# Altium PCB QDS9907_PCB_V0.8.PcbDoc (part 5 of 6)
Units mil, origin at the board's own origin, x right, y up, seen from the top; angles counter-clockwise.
Board outline 3410.03 x 4010.03 mil, 8 copper layers (Top Layer, GND1, INT1, INT2, PWR1, GND2, GND3, Bottom Layer), stack 81.668 mil thick; 250 components, 129 nets, 7010 pads, 701 vias.
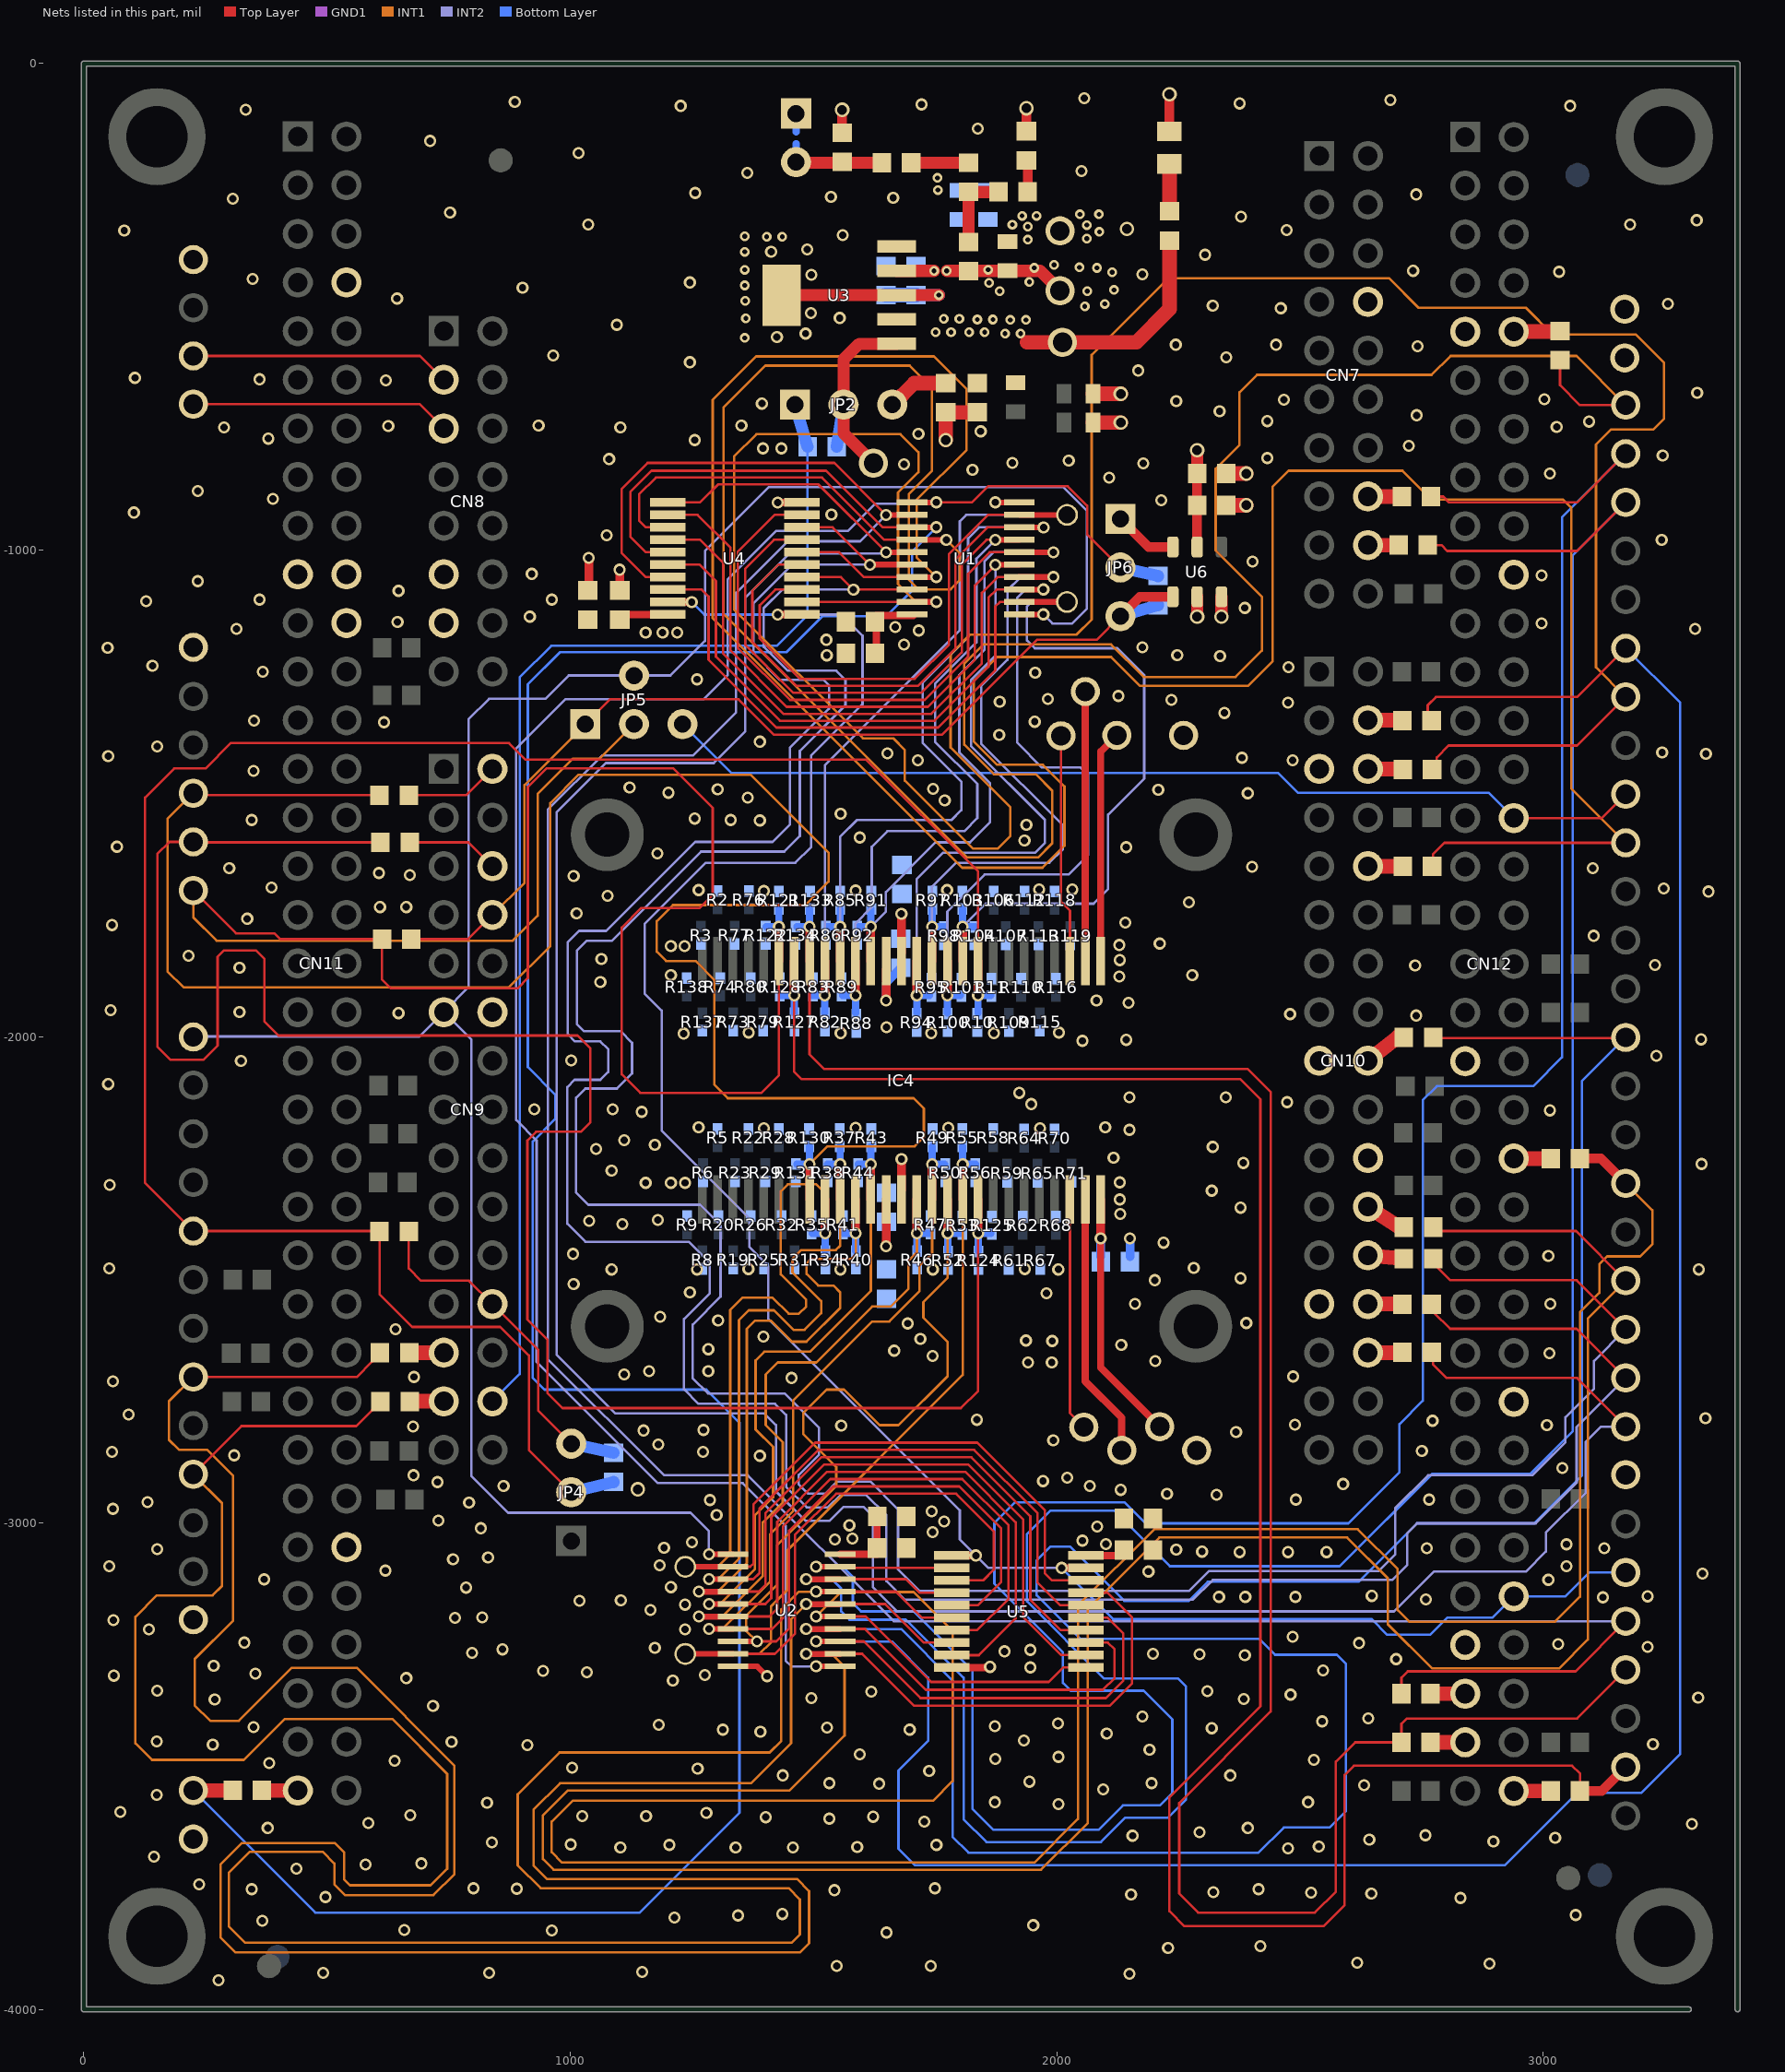
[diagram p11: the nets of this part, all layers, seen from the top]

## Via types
v1: diameter 25, hole 15, Top Layer to Bottom Layer, tented both sides, 623 vias
v2: diameter 20, hole 10, Top Layer to Bottom Layer, tented both sides, 59 vias
v3: diameter 30, hole 20, Top Layer to Bottom Layer, tented both sides, 19 vias

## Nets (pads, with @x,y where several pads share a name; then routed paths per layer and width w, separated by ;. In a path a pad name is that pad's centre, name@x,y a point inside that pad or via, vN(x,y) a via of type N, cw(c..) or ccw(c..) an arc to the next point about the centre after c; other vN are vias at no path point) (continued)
D0: IC4.9 pad.@1236.55,-3090.09 R34.2 R35.2 U2.2 U5.18 | length 2561.7
  Top Layer w5: U2.2@1334.53,-3090.09 1369.91,-3090.09 1377,-3083 1377,-2961.51 1503.51,-2835 1837,-2835 1976,-2974 1976,-3104 1990.18,-3118.18 U5.18@2060,-3118.18
  Top Layer w11.8: pad.@1236.55,-3090.09 U2.2@1334.08,-3090.09
  Top Layer w18: v1@1523.52,-2404.54 IC4.9@1523.52,-2335
  INT1 w5: pad.@1236.55,-3090.09 1302.91,-3090.09 1329,-3064 1329,-2562 1354,-2537 1416,-2537 1449,-2570 1470,-2570 1485,-2555 1485,-2541 1433,-2489 1433,-2318 1447,-2304 1506,-2304 1523.97,-2321.97 v1(1523.97,-2404.54)
  Bottom Layer w15: R35.2@1497.89,-2404.54 v1(1523.97,-2404.54) R34.2@1523.97,-2440.54
D0_1: D0.1 R33.1 U2.19 U5.2 | length 6029.7
  Top Layer w5: U2.19@1555,-3090.09 1555,-3092.59 U5.2@1784.41,-3092.59 ; R33.1@2763,-890 2795,-890 2807,-902 3070,-902 D0.1@3170,-802
  Top Layer w11.8: v1@1505.33,-3090.09 U2.19@1554.55,-3090.09
  Bottom Layer w5: v1(1505.63,-3090.24) 1560.24,-3090.24 1581,-3111 1581,-3165.05 1597.95,-3182 1706,-3182 1827,-3303 1827,-3588 1870,-3631 2086,-3631 2136.5,-3580.5 2212.5,-3580.5 2238,-3555 2238,-3404 2179,-3345 2029,-3345 2013,-3329 2013,-3266 1872,-3125 1872,-3000 1914,-2958 2140,-2958 2183,-3001 2600,-3001 2705,-2896 2705,-2797 2753,-2749 2753,-2131 2782,-2102 2980,-2102 3039,-2043 3039,-933 D0.1@3170,-802
D0_2: CN7.16 R33.2 | length 63
  Top Layer w30: CN7.16@2640,-890 R33.2@2703,-890
D1: IC4.10 R37.2 R38.2 U2.3 U5.16 | length 2503.8
  Top Layer w5: U2.3@1334.53,-3115.68 1376.32,-3115.68 1389.14,-3102.86 1389.14,-2970.58 1509.72,-2850 1830.79,-2850 1961,-2980.21 1961,-3123 2007.36,-3169.36 U5.16@2060,-3169.36
  Top Layer w11.8: v1@1284.86,-3115.68 U2.3@1334.08,-3115.68
  Top Layer w18: IC4.10@1555.02,-2335 v1(1555.02,-2262.46)
  INT1 w5: v1(1285.15,-3115.83) 1304.71,-3115.83 1347,-3073.54 1347,-2583 1367,-2563 1419,-2563 1459,-2603 1482,-2603 1516,-2569 1516,-2544 1457,-2485 1457,-2457 1475,-2439 1546,-2439 1555.02,-2429.98 v1(1555.02,-2262.46)
  Bottom Layer w15: R38.2@1528.94,-2262.46 v1(1555.02,-2262.46) R37.2@1555.02,-2226.46
D1_1: D1.1 R36.1 U2.18 U5.4 | length 6032.4
  Top Layer w5: U2.18@1555,-3115.68 1593.68,-3115.68 1690.05,-3115.68 1718.14,-3143.77 U5.4@1784.41,-3143.77 ; R36.1@2763,-990 2791,-990 2803,-1002 3070,-1002 D1.1@3170,-902
  Top Layer w11.8: v1(1485,-3115.84) U2.18@1554.7,-3115.84
  Bottom Layer w5: v1(1485,-3115.84) 1537.84,-3115.84 1557,-3135 1557,-3182 1574,-3199 1690,-3199 1809,-3318 1809,-3609 1856,-3656 2091,-3656 2141,-3606 2229,-3606 2266,-3569 2266,-3336 2250,-3320 2098,-3320 1939,-3161 1939,-3023 1987,-2975 2119,-2975 2233,-3089 2582,-3089 2772,-2899 2974,-2899 3061,-2812 3061,-1011 D1.1@3170,-902
D1_2: CN7.18 R36.2 | length 63
  Top Layer w30: CN7.18@2640,-990 R36.2@2703,-990
D2: IC4.11 R40.2 R41.2 U2.4 U5.14 | length 2516.7
  Top Layer w5: U2.4@1334.53,-3141.27 1387.73,-3141.27 1401.29,-3127.71 1401.29,-2979.65 1515.93,-2865 1824.58,-2865 1946,-2986.43 1946,-3158 2008.54,-3220.54 U5.14@2060,-3220.54
  Top Layer w11.8: v1@1264.08,-3141.43 v1(1264.53,-3141.43) U2.4@1334.23,-3141.43
  Top Layer w18: v1@1586.51,-2404.54 IC4.11@1586.51,-2335
  INT1 w5: v1(1264.53,-3141.43) 1303.58,-3141.43 1363,-3082 1363,-2601 1380,-2584 1412,-2584 1455.5,-2627.5 1485.5,-2627.5 1555,-2558 1555,-2526 1541,-2512 1510,-2512 1486,-2488 1486,-2466 1495,-2457 1577.96,-2457 1586.96,-2448 v1(1586.96,-2404.54)
  Bottom Layer w15: R41.2@1560.88,-2404.54 v1(1586.96,-2404.54) R40.2@1586.96,-2440.54
D2_1: D2.1 R39.1 U2.17 U5.6 | length 6065
  Top Layer w5: D2.1@225,-2700 561,-2700 592.5,-2668.5 592.5,-2667.5 605,-2655 R39.1@616,-2655 ; U2.17@1555,-3141.27 1669.27,-3141.27 1722.95,-3194.95 U5.6@1784.41,-3194.95
  Top Layer w11.8: v1@1505.33,-3141.27 U2.17@1554.55,-3141.27
  INT1 w5: D2.1@225,-2700 175,-2750 175,-2829 196,-2850 254,-2850 307,-2903 307,-3201 228,-3280 228,-3375 260,-3407 319,-3407 428,-3298 561,-3298 762,-3499 762,-3722 719,-3765 537,-3765 515,-3743 515,-3700 491,-3676 341,-3676 298,-3719 298,-3829 332,-3863 1455,-3863 1472,-3846 1472,-3774 1449,-3751 939,-3751 892,-3704 892,-3558 978,-3472 1410,-3472 1434,-3448 1434,-3178 1470.58,-3141.43 v1(1505.63,-3141.43)
D2_2: CN9.25 R39.2 | length 64
  Top Layer w30: R39.2@676,-2650 CN9.25@740,-2650
D3: IC4.12 R43.2 R44.2 U2.5 U5.12 | length 2545.8
  Top Layer w5: U2.5@1334.53,-3166.86 1401.14,-3166.86 1413.43,-3154.57 1413.43,-2988.72 1522.15,-2880 1818.36,-2880 1931,-2992.64 1931,-3193 2009.73,-3271.73 U5.12@2060,-3271.73
  Top Layer w11.8: v1@1285.15,-3166.86 U2.5@1334.53,-3166.86
  Top Layer w18: IC4.12@1618.01,-2335 v1(1618.01,-2262.46)
  INT1 w5: v1(1285.15,-3167.02) 1307.99,-3167.02 1380,-3095 1380,-2984 1417,-2947 1417,-2844 1381,-2808 1381,-2666 1399,-2648 1493,-2648 1618.01,-2522.99 v1(1618.01,-2262.46)
  Bottom Layer w15: R44.2@1591.93,-2262.46 v1(1618.01,-2262.46) R43.2@1618.01,-2226.46
D3_1: D3.1 R42.2 U2.16 U5.8 | length 6084.4
  Top Layer w5: D3.1@225,-2900 324,-2801 560,-2801 592.5,-2768.5 593.5,-2768.5 610,-2752 R42.2@610,-2751 ; U2.16@1555,-3166.86 1647.86,-3166.86 1727.13,-3246.13 U5.8@1784.41,-3246.13
  Top Layer w11.8: v1(1485,-3167.02) U2.16@1554.7,-3167.02
  INT1 w5: D3.1@237,-2900 D3.1@225,-2900 284,-2959 284,-3130 265,-3149 150,-3149 106,-3193 106,-3453 140,-3487 329,-3487 413,-3403 634,-3403 747,-3516 747,-3711 713,-3745 547,-3745 535,-3733 535,-3677 516,-3658 325,-3658 281,-3702 281,-3852 312,-3883 1472,-3883 1491,-3864 1491,-3757 1466,-3732 952,-3732 924.5,-3704.5 924.5,-3589.5 979,-3535 1372,-3535 1454,-3453 1454,-3198.02 v1(1485,-3167.02)
D3_2: CN9.27 R42.1 | length 63
  Top Layer w30: R42.1@677,-2750 CN9.27@740,-2750
D4: IC4.15 R46.2 R47.2 U2.6 U5.9 | length 2513.8
  Top Layer w5: U2.6@1334.53,-3192.45 1409.55,-3192.45 1425.57,-3176.43 1425.57,-2997.79 1528.36,-2895 1812.15,-2895 1916,-2998.85 1916,-3196 1840,-3272 1784.68,-3272 U5.9@1784.41,-3271.73
  Top Layer w11.8: v1@1264.08,-3192.61 v1(1264.53,-3192.61) U2.6@1334.23,-3192.61
  Top Layer w18: v1@1712.5,-2404.54 IC4.15@1712.5,-2335
  INT1 w5: v1(1264.53,-3192.61) 1312.39,-3192.61 1396,-3109 1396,-2999 1437,-2958 1437,-2834 1402,-2799 1402,-2695 1427,-2670 1506,-2670 1621,-2555 1659,-2555 1695,-2519 1695,-2462 1712.94,-2444.06 v1(1712.94,-2404.54)
  Bottom Layer w15: R46.2@1712.94,-2440.54 v1(1712.94,-2404.54) R47.2@1739.02,-2404.54
D4_1: D4.1 R45.1 U2.15 U5.11 | length 6088.9
  Top Layer w5: U2.15@1555,-3192.45 1607.45,-3192.45 1742,-3327 1984,-3327 2013.68,-3297.32 U5.11@2060,-3297.32
  Top Layer w11.8: v1@1505.33,-3192.45 U2.15@1554.55,-3192.45
  Top Layer w20: R45.1@3076,-2251 3119,-2251 D4.1@3170,-2302
  INT1 w5: v1(1505.63,-3192.61) 1556.23,-3142 1706,-3142 1786,-3222 1786,-3531 1746,-3571 1005,-3571 962,-3614 962,-3677 983,-3698 1954.47,-3698 2044,-3608.47 2044,-3170 2201,-3013 2619,-3013 2701,-3095 2701,-3179 2725,-3203 3025,-3203 3076,-3152 3076,-2567 3116,-2527 3116,-2468 3132,-2452 3200,-2452 3225,-2427 3225,-2357 D4.1@3170,-2302
D4_2: CN12.44 R45.2 | length 76
  Top Layer w30: CN12.44@2940,-2251 R45.2@3016,-2251
D5: IC4.16 R49.2 R50.2 U2.7 U5.7 | length 2504.4
  Top Layer w5: U2.7@1334.53,-3218.04 1414.96,-3218.04 1437.71,-3195.29 1437.71,-3006.86 1534.57,-2910 1805.94,-2910 1901,-3005.07 1901,-3156 1836.46,-3220.54 U5.7@1784.41,-3220.54
  Top Layer w11.8: v1@1284.86,-3218.04 U2.7@1334.08,-3218.04
  Top Layer w18: IC4.16@1743.99,-2335 v1(1743.99,-2262.46)
  INT1 w5: v1(1285.15,-3218.2) 1312.8,-3218.2 1411,-3120 1411,-3023 1458,-2976 1458,-2749 1621,-2586 1656,-2586 1718,-2524 1718,-2472 1743.99,-2446.01 v1(1743.99,-2262.46)
  Bottom Layer w15: R49.2@1743.99,-2226.46 v1(1743.99,-2262.46) R50.2@1770.07,-2262.46
D5_1: D5.1 R48.1 U2.14 U5.13 | length 6043.8
  Top Layer w5: U2.14@1555,-3218.04 1606.04,-3218.04 1731,-3343 2095,-3343 2119,-3319 2119,-3260 2105.13,-3246.13 U5.13@2060,-3246.13 ; R48.1@2761,-2001 2763,-2003 D5.1@3169,-2003
  Top Layer w11.8: v1(1485,-3218.2) U2.14@1554.7,-3218.2
  Bottom Layer w5: v1(1485,-3218.2) 1680.2,-3218.2 1786,-3324 1786,-3645 1819,-3678 2415,-3678 2467,-3626 2561,-3626 2595,-3592 2595,-3290 2576,-3271 2449,-3271 2416,-3238 2048,-3238 1959,-3149 1959,-3077 1987,-3049 2028,-3049 2139,-3160 2272,-3160 2311,-3121 2621,-3121 2741,-3001 2982,-3001 3080,-2903 3080,-2092 D5.1@3170,-2002
D5_2: CN10.18 R48.2 | length 78.2
  Top Layer w30: CN10.18@2640,-2050 R48.2@2701,-2001
D6: IC4.17 R52.2 R53.2 U2.8 U5.5 | length 2507.6
  Top Layer w5: v1(1383.75,-3243.63) 1423.37,-3243.63 1449.86,-3217.14 1449.86,-3015.93 1540.79,-2925 1799.72,-2925 1886,-3011.28 1886,-3121 1837.64,-3169.36 U5.5@1784.41,-3169.36
  Top Layer w11.8: U2.8@1334.53,-3243.63 v1(1383.75,-3243.63)
  Top Layer w18: v1@1775.49,-2404.54 IC4.17@1775.49,-2335
  INT1 w5: v1(1383.75,-3243.63) 1361.5,-3221.39 1361.5,-3191.5 1425,-3128 1425,-3046 1547,-2924 1547,-2885 1479,-2817 1479,-2774 1527,-2726 1563,-2726 1636,-2799 1675,-2799 1775.94,-2698.06 1775.94,-2627.94 1726,-2578 1726,-2546 1775.94,-2496.06 v1(1775.94,-2404.54)
  Bottom Layer w15: R52.2@1775.94,-2440.54 v1(1775.94,-2404.54) R53.2@1802.02,-2404.54
D6_1: D6.1 R51.1 U2.13 U5.15 | length 6041.8
  Top Layer w5: U2.13@1555,-3243.63 1603.63,-3243.63 1720,-3360 2101,-3360 2137,-3324 2137,-3227 2104.95,-3194.95 U5.15@2060,-3194.95 ; R51.1@2763,-1350 2763,-1319 2780,-1302 3070,-1302 D6.1@3170,-1202
  Top Layer w11.8: v1@1505.33,-3243.63 U2.13@1554.55,-3243.63
  Bottom Layer w5: v1(1505.63,-3243.79) 1661.79,-3243.79 1736,-3318 1736,-3448 1675,-3509 1675,-3670 1709,-3704 2921,-3704 3070,-3555 3202,-3555 3282,-3475 3282,-1314 D6.1@3170,-1202
D6_2: CN10.4 R51.2 | length 63
  Top Layer w30: CN10.4@2640,-1350 R51.2@2703,-1350
D7: IC4.18 pad.@1236.55,-3269.23 R55.2 R56.2 U2.9 U5.3 | length 2562.5
  Top Layer w5: U2.9@1334.53,-3269.23 1420.78,-3269.23 1462,-3228 1462,-3025 1547,-2940 1793.51,-2940 1871,-3017.49 1871,-3096 1848.82,-3118.18 U5.3@1784.41,-3118.18
  Top Layer w11.8: pad.@1236.55,-3269.23 U2.9@1334.08,-3269.23
  Top Layer w18: IC4.18@1806.98,-2335 v1(1806.98,-2262.46)
  INT1 w5: pad.@1236.55,-3269.23 1388.77,-3269.23 1413,-3245 1413,-3171 1446,-3138 1446,-3056.97 1806.98,-2695.98 v1(1806.98,-2262.46)
  Bottom Layer w15: R55.2@1806.98,-2226.46 v1(1806.98,-2262.46) R56.2@1833.06,-2262.46
D7_1: D7.1 R54.1 U2.12 U5.17 | length 6104.8
  Top Layer w5: U2.12@1555,-3269.23 1600.23,-3269.23 1707,-3376 2109,-3376 2155,-3330 2155,-3194 2104.77,-3143.77 U5.17@2060,-3143.77 ; R54.1@2764,-2392 2772,-2400 3068,-2400 D7.1@3170,-2502
  Top Layer w11.8: v1@1484.55,-3269.38 v1(1485,-3269.38) U2.12@1554.7,-3269.38
  INT1 w5: v1(1485,-3269.38) 1537.38,-3269.38 1564,-3296 1564,-3437 1451,-3550 995,-3550 944,-3601 944,-3691 966,-3713 1968,-3713 2064,-3617 2064,-3177 2211,-3030 2597,-3030 2681,-3114 2681,-3208 2772,-3299 3033,-3299 3092,-3240 3092,-2580 D7.1@3170,-2502
D7_2: CN10.24 R54.2 | length 76.6
  Top Layer w30: CN10.24@2640,-2350 R54.2@2704,-2392
D8: IC4.37 pad.@2021,-1106.91 R103.2 R104.2 U1.2 U4.18 | length 2558.7
  Top Layer w5: U4.18@1200.5,-1081.32 1270.32,-1081.32 1284.5,-1095.5 1284.5,-1225.5 1424,-1365 1756.49,-1365 1874,-1247.49 1874,-1116 1883.09,-1106.91 U1.2@1923.47,-1106.91
  Top Layer w11.8: U1.2@1923.47,-1106.91 pad.@2021,-1106.91
  Top Layer w18: IC4.37@1806.94,-1845 v1(1806.94,-1774.46)
  INT2 w5: v1(1806.94,-1774.46) 1854.39,-1727 2076,-1727 2106,-1697 2106,-1544 2180,-1470 2180,-1257 2125,-1202 1955,-1202 1939,-1186 1939,-1116 1948.09,-1106.91 pad.@2021,-1106.91
  Bottom Layer w15: R103.2@1806.94,-1738.46 v1(1806.94,-1774.46) R104.2@1833.02,-1774.46
D8_1: D8.1 R102.1 U1.19 U4.2 | length 6097.1
  Top Layer w5: U4.2@1476.09,-1106.91 U1.19@1703,-1106.91 ; R102.1@2772,-1451 2781.57,-1441.43 2781.57,-1426.43 2806,-1402 3070,-1402 D8.1@3170,-1302
  Top Layer w11.8: U1.19@1703,-1106.91 v1@1751.77,-1106.91
  INT1 w5: v1(1752.37,-1106.76) 1710.76,-1106.76 1674,-1070 1674,-882 1716,-840 1716,-799 1679,-762 1383,-762 1337,-808 1337,-1122 1602,-1387 1664,-1387 1688,-1411 1688,-1474 1828,-1614 1879,-1614 1905,-1588 1905,-1529 1782,-1406 1782,-1214 1822,-1174 2041,-1174 2072,-1143 2072,-599 2230,-441 2683,-441 2744,-502 2965,-502 3020,-557 3191,-557 3249,-615 3249,-730 3227,-752 3140,-752 3109,-783 3109,-1241 D8.1@3170,-1302
D8_2: CN10.6 R102.2 | length 63
  Top Layer w30: CN10.6@2640,-1450 R102.2@2703,-1450
D9: IC4.38 R100.2 R101.2 U1.3 U4.16 | length 2530.1
  Top Layer w5: U4.16@1200.5,-1030.14 1266.14,-1030.14 1299.5,-1063.5 1299.5,-1219.29 1431.34,-1351.13 1749.15,-1351.13 1860,-1240.28 1860,-1098 1876.68,-1081.32 U1.3@1923.47,-1081.32
  Top Layer w11.8: U1.3@1923.47,-1081.32 v1@1972.24,-1081.32
  Top Layer w18: v1(1775.49,-1915.54) IC4.38@1775.49,-1845
  INT2 w5: v1(1775.49,-1915.54) 1775.49,-1743.51 1852,-1667 2025,-1667 2065,-1627 2065,-1463 2049,-1447 1970,-1447 1919,-1396 1919,-1098 1935.83,-1081.17 v1(1972.85,-1081.17)
  Bottom Layer w15: R100.2@1775.49,-1951.54 v1(1775.49,-1915.54) R101.2@1801.57,-1915.54
D9_1: D9.1 R99.1 U1.18 U4.4 | length 6093.9
  Top Layer w5: U4.4@1476.09,-1055.73 1556.73,-1055.73 v1(1582.32,-1081.32) U1.18@1703,-1081.32 ; R99.1@2764,-2456 2809,-2501 3069,-2501 D9.1@3170,-2602
  INT2 w5: v1(1582.32,-1081.32) 1435.68,-1081.32 1397.98,-1119.02 1397.98,-1198.98 1447,-1248 1547,-1248 1566,-1267 1566,-1319 1472,-1413 1472,-1588 1440,-1620 1269,-1620 1086,-1803 1034,-1803 1014,-1823 1014,-1975 1028,-1989 1103,-1989 1127,-2013 1127,-2076 1096,-2107 1031,-2107 1012,-2126 1012,-2321 1037,-2346 1267,-2346 1309,-2388 1309,-2535 1252,-2592 1252,-2703 1283,-2734 1441,-2734 1511.5,-2804.5 1511.5,-2859.5 1470,-2901 1470,-2921 1489,-2940 1524,-2940 1549,-2915 1617,-2915 1674,-2972 1674,-3095.5 1718.5,-3140 2272,-3140 2313,-3099 2662,-3099 2696,-3065 2696,-2970 2764,-2902 2978,-2902 3046,-2834 3046,-2783 3105,-2724 3105,-2667 D9.1@3170,-2602
D9_2: CN10.26 R99.2 | length 64.3
  Top Layer w30: CN10.26@2640,-2450 R99.2@2704,-2456
D10: IC4.39 R97.2 R98.2 U1.4 U4.14 | length 2497.8
  Top Layer w5: U4.14@1200.5,-978.96 1266.96,-978.96 1314.5,-1026.5 1314.5,-1213.07 1438.18,-1336.75 1742.32,-1336.75 1846,-1233.07 1846,-1088 1878.27,-1055.73 U1.4@1923.47,-1055.73
  Top Layer w11.8: U1.4@1922.87,-1055.58 v1@1993.02,-1055.58
  Top Layer w18: IC4.39@1743.94,-1845 v1(1743.94,-1774.46)
  INT2 w5: v1(1743.94,-1774.46) 1743.94,-1692.06 1793,-1643 1985,-1643 2013,-1615 2013,-1566 1845,-1398 1845,-1280 1899,-1226 1899,-1083 1926.42,-1055.58 v1(1993.47,-1055.58)
  Bottom Layer w15: R97.2@1743.94,-1738.46 v1(1743.94,-1774.46) R98.2@1770.02,-1774.46
D10_1: D10.1 R96.1 U1.17 U4.6 | length 6069.1
  Top Layer w5: U4.6@1476.09,-1004.55 1552.55,-1004.55 1603.73,-1055.73 U1.17@1703,-1055.73 ; R96.1@2772,-1650 2773.57,-1648.43 2773.57,-1625.43 2797,-1602 D10.1@3170,-1602
  Top Layer w11.8: U1.17@1702.55,-1055.73 v1@1751.77,-1055.73
  INT1 w5: v1(1752.37,-1055.58) 1712,-1015.2 1712,-897 1815,-794 1815,-669 1748,-602 1382,-602 1293,-691 1293,-1140 1806,-1653 1971,-1653 2016,-1608 2016,-1486 1971.5,-1441.5 1877.5,-1441.5 1830,-1394 1830,-1268 1878,-1220 2112,-1220 2171,-1279 2394,-1279 2444,-1229 2444,-870 2477,-837 2711,-837 2770,-896 3041,-896 3058,-913 3058,-1490 D10.1@3170,-1602
D10_2: CN10.10 R96.2 | length 63
  Top Layer w30: CN10.10@2640,-1650 R96.2@2703,-1650
D11: IC4.40 R94.2 R95.2 U1.5 U4.12 | length 2542.8
  Top Layer w5: U4.12@1200.5,-927.78 1261.77,-927.78 1329.5,-995.5 1329.5,-1206.86 1445.01,-1322.38 1735.48,-1322.38 1832,-1225.85 1832,-1072.84 v1@1874.7,-1030.14 ; U1.5@1923.02,-1030.14 U1.5@1923.47,-1030.14
  Top Layer w11.8: v1@1874.7,-1030.14 U1.5@1923.02,-1030.14
  Top Layer w18: v1(1712.5,-1915.54) IC4.40@1712.5,-1845
  INT1 w5: v1@1712,-1915.05 v1(1712.5,-1915.54)
  INT2 w5: v1@1712,-1915.05 1712,-1677 1767,-1622 1956,-1622 1976,-1602 1976,-1555 1824,-1403 1824,-1267 1874.1,-1216.9 v1(1874.1,-1030.29)
  Bottom Layer w15: R94.2@1712.5,-1951.54 v1(1712.5,-1915.54) R95.2@1738.58,-1915.54
D11_1: D11.1 R93.1 U1.16 U4.8 | length 6079.7
  Top Layer w5: U4.8@1476.09,-953.37 1539.37,-953.37 v1(1616.14,-1030.14) ; R93.1@2763,-2550 2763,-2555 2775.5,-2567.5 2809,-2601 3069,-2601 D11.1@3170,-2702
  Top Layer w12: v1(1616.14,-1030.14) U1.16@1703,-1030.14
  INT2 w5: v1(1616.14,-1030.14) 1455.85,-1030.14 1377,-1108.98 1377,-1212.25 1431.75,-1267 1521,-1267 1532,-1278 1532,-1326 1452,-1406 1452,-1564 1416,-1600 1257,-1600 1074,-1783 1018,-1783 995,-1806 995,-1995 1010,-2010 1062,-2010 1078,-2026 1078,-2073 1062,-2089 1009,-2089 994,-2104 994,-2385 1031,-2422 1244,-2422 1287,-2465 1287,-2528 1234,-2581 1234,-2725 1264,-2755 1421,-2755 1444,-2778 1444,-2926 1486,-2968 1530,-2968 1556,-2942 1608,-2942 1650,-2984 1650,-3119.5 1688.5,-3158 2280,-3158 2321,-3117 2690,-3117 2721,-3086 2721,-3021 2741,-3001 2985,-3001 3069,-2917 3069,-2803 D11.1@3170,-2702
D11_2: CN10.28 R93.2 | length 63
  Top Layer w30: CN10.28@2640,-2550 R93.2@2703,-2550
D12: IC4.43 R91.2 R92.2 U1.6 U4.9 | length 2502.7
  Top Layer w5: U4.9@1475.81,-927.5 1420.5,-927.5 1344.5,-1003.5 1344.5,-1200.65 1451.85,-1308 1728.64,-1308 1818,-1218.64 1818,-1049 1862.45,-1004.55 U1.6@1923.47,-1004.55
  Top Layer w11.8: U1.6@1923.47,-1004.55 v1(1993.63,-1004.55)
  Top Layer w18: IC4.43@1618.01,-1845 v1(1617.96,-1774.46)
  INT2 w5: v1(1617.96,-1774.46) 1649,-1743.42 1649,-1703 1751,-1601 1822,-1601 1863,-1560 1863,-1479 1800,-1416 1800,-1257 1852,-1205 1852,-1023 1870.45,-1004.55 v1(1993.63,-1004.55)
  Bottom Layer w15: R92.2@1591.88,-1774.46 v1(1617.96,-1774.46) R91.2@1617.96,-1738.46
D12_1: D12.1 R90.1 U1.15 U4.11 | length 6079.3
  Top Layer w5: U4.11@1200.5,-902.19 1266.82,-902.19 1304,-865 1510,-865 v1@1652.05,-1007.05 ; R90.1@2771,-2649 2773.57,-2651.57 2773.57,-2673.57 2802,-2702 3070,-2702 D12.1@3170,-2802
  Top Layer w11.8: v1(1649.55,-1004.55) U1.15@1703,-1004.55
  INT2 w5: v1@1652.65,-1006.89 1451.11,-1006.89 1360,-1098 1360,-1373 1295,-1438 1073,-1438 972,-1539 972,-2654 1093,-2775 1399,-2775 1423,-2799 1423,-2935 1484,-2996 1533,-2996 1562,-2967 1603,-2967 1622,-2986 1622,-3132 1672,-3182 2693.76,-3182 2775.76,-3100 2965,-3100 3006,-3059 3006,-3020 3088,-2938 3088,-2833 3119,-2802 D12.1@3170,-2802
D12_2: CN10.30 R90.2 | length 63
  Top Layer w30: CN10.30@2640,-2650 R90.2@2703,-2650
D13: IC4.44 R88.2 R89.2 U1.7 U4.7 | length 2490.7
  Top Layer w5: U4.7@1476.09,-978.96 1419.04,-978.96 1359.5,-1038.5 1359.5,-1194.44 1458.69,-1293.63 1721.8,-1293.63 1805,-1210.43 1805,-1030 1856.04,-978.96 v1(1873.8,-978.96)
  Top Layer w11.8: v1(1873.8,-978.96) U1.7@1923.02,-978.96
  Top Layer w18: v1(1586.51,-1915.54) IC4.44@1586.51,-1845
  INT2 w5: v1(1586.51,-1915.54) 1586.51,-1767.49 1620,-1734 1620,-1610 1652,-1578 1810,-1578 1837,-1551 1837,-1481 1750,-1394 1750,-1275 1835,-1190 1835,-1017.76 v1(1873.8,-978.96)
  Bottom Layer w15: R89.2@1560.43,-1915.54 v1(1586.51,-1915.54) R88.2@1586.51,-1951.54
D13_1: D13.1 R87.1 U1.14 U4.13 | length 6084.6
  Top Layer w5: U4.13@1200.5,-953.37 1155.37,-953.37 1141.5,-939.5 1141.5,-885.5 1176,-851 1518,-851 1645.96,-978.96 U1.14@1703,-978.96 ; R87.1@3035,-610 3035,-661 3076,-702 D13.1@3170,-702
  Top Layer w11.8: U1.14@1703,-978.96 v1(1773.15,-978.96)
  INT1 w5: v1(1773.15,-978.96) 1801,-1006.8 1801,-1062 1782,-1081 1716,-1081 1696,-1061 1696,-885 1743.94,-837.06 1743.94,-666.94 1698,-621 1401,-621 1315,-707 1315,-1131 1816,-1632 1962,-1632 1991,-1603 1991,-1495 1957,-1461 1871,-1461 1810,-1400 1810,-1233 1849,-1194 2112,-1194 2179,-1261 2368,-1261 2422,-1207 2422,-1096 2327,-1001 2327,-833 2376,-784 2376,-676 2412,-640 2771,-640 2810,-601 3069,-601 D13.1@3170,-702
D13_2: CN12.10 R87.2 | length 95
  Top Layer w30: CN12.10@2940,-551 R87.2@3035,-551
D14: IC4.45 R85.2 R86.2 U1.8 U4.5 | length 2495.7
  Top Layer w5: U4.5@1476.09,-1030.14 1427.86,-1030.14 1374.5,-1083.5 1374.5,-1188.22 1465.53,-1279.25 1714.96,-1279.25 1792,-1202.21 1792,-1019 1857.63,-953.37 U1.8@1923.02,-953.37
  Top Layer w11.8: U1.8@1923.92,-953.37 v1(1973.14,-953.37)
  Top Layer w18: IC4.45@1555.02,-1845 v1(1554.97,-1774.46)
  INT2 w5: v1(1554.97,-1774.46) 1554.97,-1590.03 1590,-1555 1784,-1555 1804,-1535 1804,-1476 1725,-1397 1725,-1272 1818,-1179 1818,-976 1840.63,-953.37 v1(1973.14,-953.37) ; v1@1973.14,-954 v1@1979,-954
  Bottom Layer w15: R86.2@1528.89,-1774.46 v1(1554.97,-1774.46) R85.2@1554.97,-1738.46
D14_1: D14.1 R84.1 U1.13 U4.15 | length 6032.2
  Top Layer w5: R84.1@306,-3550 R84.1@315,-3550 ; U4.15@1200.5,-1004.55 1155.55,-1004.55 1123.5,-972.5 1123.5,-880.5 1167,-837 1526,-837 1642.37,-953.37 U1.13@1702.55,-953.37
  Top Layer w11.8: U1.13@1702.55,-953.37 U1.13@1703,-953.37 v1@1751.77,-953.37
  Top Layer w30: D14.1@225,-3550 R84.1@306,-3550
  Bottom Layer w5: D14.1@225,-3550 476,-3801 1143,-3801 1348,-3596 1348,-2794 1280,-2726 947,-2726 923,-2702 923,-2216 969,-2170 969,-2119 913,-2063 913,-1276 979,-1210 1445,-1210 1519,-1136 1650,-1136 1703,-1083 1703,-1002.59 v1(1752.37,-953.21)
D14_2: CN11.69 R84.2 | length 65
  Top Layer w30: R84.2@375,-3550 CN11.69@440,-3550
D15: IC4.46 pad.@2021.45,-927.78 R82.2 R83.2 U1.9 U4.3 | length 2531.3
  Top Layer w5: U4.3@1476.09,-1081.32 1421.68,-1081.32 1389.5,-1113.5 1389.5,-1182.01 1472.37,-1264.88 1708.12,-1264.88 1779,-1194 1779,-1008 1859.22,-927.78 U1.9@1923.47,-927.78 U1.9@1923.92,-927.78
  Top Layer w11.8: U1.9@1923.92,-927.78 pad.@2021.45,-927.78
  Top Layer w18: v1(1523.52,-1915.54) IC4.46@1523.52,-1845
  INT2 w5: v1(1523.52,-1915.54) 1523.52,-1442.48 1801,-1165 1801,-940.98 1814.21,-927.78 pad.@2021.45,-927.78
  Bottom Layer w15: R83.2@1497.44,-1915.54 v1(1523.52,-1915.54) R82.2@1523.52,-1951.54
D15_1: D15.1 R81.1 U1.12 U4.17 | length 6112.2
  Top Layer w5: U4.17@1200.5,-1055.73 1155.73,-1055.73 1105.5,-1005.5 1105.5,-874.5 1159,-821 1542.77,-821 v1(1649.55,-927.78) ; R81.1@2709,-3351 2709,-3318 2722,-3305 3067,-3305 D15.1@3170,-3202
  Top Layer w11.8: v1(1649.55,-927.78) U1.12@1703,-927.78
  INT2 w5: v1(1649.55,-927.78) 1649.55,-928.45 1596,-982 1447,-982 1341,-1088 1341,-1334 1253,-1422 1066,-1422 954,-1534 954,-2663 1193,-2902 1365,-2902 1665,-3202 D15.1@3170,-3202
D15_2: CN12.65 R81.2 | length 54
  Top Layer w30: R81.2@2786,-3351 CN12.65@2840,-3351
GND: C7.2 C8.2 C9.2 C10.2 C11.2 C12.2 C13.2 C14.2 C15.2 C16.2 C19.2 C20.2 C21.2 C22.2 C23.2 C24.2 C25.2 C26.2 C27.2 C28.2 C29.2 C30.2 CN7.8 CN8.11 CN8.13 CN9.12 CN10.5 CN10.17 CN10.22 CN10.27 CN11.8 CN11.19 CN11.20 CN11.22 CN11.60 CN12.9 CN12.20 CN12.39 CN12.54 CN12.63 GND2.1 GND3.1 GND4.1 GND5.1 IC4.14 IC4.42 JP12.1 LED2.C pad.1@225,-403 pad.1@225,-3199 pad.1@3168,-505 pad.1@3170,-2901 R3.1 R6.1 R9.1 R11.1 R13.2 R20.1 R23.1 R26.1 R29.1 R32.1 R35.1 R38.1 R41.1 R44.1 R47.1 R50.1 R53.1 R56.1 R59.1 R62.1 R65.1 R68.1 R71.1 R74.1 R77.1 R80.1 R83.1 R86.1 R89.1 R92.1 R95.1 R98.1 R101.1 R104.1 R107.1 R110.1 R113.1 R116.1 R119.1 R122.1 R125.1 R128.1 R131.1 R134.1 R138.1 R140.2 R141.1 U1.10 U2.10 U3.3 U4.10 U5.10 U6.2 U6.3 | length 1690.4
  Top Layer w11.8: U2.10@1334.08,-3294.82 1384.37,-3294.82 v1@1404.55,-3315 ; v1@1873.8,-902.19 U1.10@1923.02,-902.19
  Top Layer w15: v1@1426.87,-902.19 U4.10@1476.09,-902.19 ; U5.10@1784.41,-3297.32 v1@1863,-3297.32
  Top Layer w18: C29.2@1036,-1083 1038,-1081 v1(1038,-1016) ; v1(1101.5,-1040.5) 1101.5,-1082.5 C30.2@1102,-1083 ; v1(1649.5,-1926) IC4.42@1649.5,-1862 ; IC4.14@1681,-2316 v1(1681,-2252)
  Top Layer w20: R140.2@1559,-142 v3(1559,-95) ; R13.2@1938,-139 v3(1938,-92) ; LED2.C@2232,-139.31 v3(2232,-63.31)
  Top Layer w25: U3.3@1434.89,-476.13 U3.3@1671.11,-476.13 v2(1758,-476.13) ; v3(2289,-1137.18) U6.2@2289,-1096.18 ; v3(2339,-1137.18) U6.3@2339,-1096.18
  Top Layer w30: v3(1772,-774) C11.2@1772,-717 C12.2@1833,-717 ; C19.2@2075,-738 v3(2132,-738) ; C20.2@2075,-679 v3(2132,-679) ; C15.2@2349,-908 v3(2390,-908) ; C16.2@2349,-843 v3(2390,-843)
  GND1 w15: CN11.19@440,-1048.59 ccw(c441.71,-1046.88) CN11.19@441.71,-1049.29 ; CN11.60@540,-3048.59 ccw(c541.71,-3046.88) CN11.60@541.71,-3049.29 ; CN11.22@540,-1148.59 ccw(c541.71,-1146.88) CN11.22@541.71,-1149.29 ; CN11.20@540,-1048.59 ccw(c541.71,-1046.88) CN11.20@541.71,-1049.29 ; CN11.8@540,-448.59 ccw(c541.71,-446.88) CN11.8@541.71,-449.29 ; CN8.13@740,-1150 ccw(c741.71,-1148.29) CN8.13@741.71,-1150.71 ; CN8.11@740,-1050 ccw(c741.71,-1048.29) CN8.11@741.71,-1050.71 ; CN9.12@840,-1950 ccw(c841.71,-1948.29) CN9.12@841.71,-1950.71 ; JP12.1@1464.35,-101.24 ccw(c1466.06,-99.53) JP12.1@1466.06,-101.94 ; CN10.5@2540,-1450 ccw(c2541.71,-1448.29) CN10.5@2541.71,-1450.71 ; CN10.22@2638.29,-2249.29 ccw(c2640,-2247.59) CN10.22@2640,-2250 ; CN12.63@2840,-3249.59 ccw(c2841.71,-3247.88) CN12.63@2841.71,-3250.29 ; CN12.39@2840,-2049.59 ccw(c2841.71,-2047.88) CN12.39@2841.71,-2050.29 ; CN12.9@2840,-549.59 ccw(c2841.71,-547.88) CN12.9@2841.71,-550.29 ; CN12.54@2940,-2749.59 ccw(c2941.71,-2747.88) CN12.54@2941.71,-2750.29 ; CN12.20@2940,-1049.59 ccw(c2941.71,-1047.88) CN12.20@2941.71,-1050.29 ; CN10.17@2540,-2050 ccw(c2541.71,-2048.29) 2541.71,-2050.71 cw(c2541.71,-2048.29) CN10.17@2540,-2050
  INT1 w15: CN11.60@540,-3048.59 ccw(c541.71,-3046.88) CN11.60@541.71,-3049.29 ; CN12.20@2940,-1049.59 ccw(c2941.71,-1047.88) CN12.20@2941.71,-1050.29
  INT2 w15: CN10.27@2540.52,-2549.49 CN10.27@2540,-2550 CN10.27@2541.23,-2551.2 ; CN10.17@2540.52,-2049.49 CN10.17@2540,-2050 CN10.17@2541.23,-2051.2
  Bottom Layer w15: 1464.35,-140.65 JP12.1@1464.35,-102.65
  Bottom Layer w18: v1(1649.5,-1926) 1649.5,-1889.5 C24.2@1680,-1859 ; R141.1@2150.9,-2452.45 v1(2150.9,-2415)
  Bottom Layer w25: C13.2@1711,-476.13 v2(1758,-476.13)
  Bottom Layer w30: C14.2@1649,-476.13 C13.2@1711,-476.13
  other v1: 277,-3940 2150,-3927 492,-3925 833,-3925 1148,-3923 1548,-3911 1741,-3911 2890,-3906 2618,-3904 2229,-3874 2419,-3870 1650,-3842 962,-3838 659,-3837 1952,-3827 367,-3818 1214,-3811 1345,-3807 3067,-3806 1436,-3804 2830,-3771 497,-3769 2153,-3764 2647,-3762 2523,-3760 2322,-3759 1543,-3755 345,-3753 2415,-3753 890,-3752 801,-3751 1750,-3751 237,-3743 437,-3711 579,-3702 694,-3700 144,-3686 2476,-3669 1103,-3667 1340,-3667 1458,-3667 1590,-3666 2539,-3665 1204,-3662 1753,-3662 1001,-3661 839,-3657 2898,-3655 2643,-3651 3025,-3647 2156,-3643 2758,-3642 2294,-3636 378,-3627 2393,-3627 3306,-3619 585,-3617 1728,-3614 1533,-3608 1402,-3605 1622.5,-3604 1025,-3603 1156,-3603 671,-3601 1280,-3596 75,-3594 2004,-3578 829,-3575 1873,-3574 2517,-3574 150,-3559 2096,-3548 2632,-3539 1635,-3536 1533,-3535 2195,-3535 1944,-3532 1437,-3519 2357,-3519 1738,-3510 1262,-3505 1004,-3503 381,-3494 639,-3489 2529,-3487 1873.8,-3485 2004,-3481 1595,-3476 2191,-3466 912,-3457 265,-3456 3226,-3455 756,-3450 150,-3449 1933,-3447 2103,-3433 1391,-3429 1314,-3425 1698,-3425 2319,-3422 1528,-3421 349,-3420 1873,-3418 1182,-3415 2003,-3412 2546,-3408 2641,-3402 2176,-3398 718,-3376 269,-3363 2385,-3362 1496,-3360 3319,-3359 2481,-3353 1619,-3347 2310,-3346 151,-3345 1211,-3324 663,-3319 1404.85,-3315.15 62,-3314 1277,-3313 353,-3310 1034,-3307 944,-3304 2548,-3303 1946,-3297 1863,-3296 267,-3294 2698,-3280 2387,-3272 2294,-3270 2198,-3269 798,-3267 1893,-3264 1946,-3261 861,-3260 1174,-3257 3215,-3255 3031,-3249 2622,-3247 330,-3246 2485,-3234 134,-3219 1236,-3219 61,-3200 763,-3195 819,-3194 1165,-3179 1236,-3168 1019,-3160 1104,-3159 2759,-3157 3123,-3153 2334,-3152 2388,-3152 2491,-3152 3215,-3151 2648,-3150 786,-3133 1207,-3132 3011,-3117 371,-3116 3328,-3104 2189,-3100 620,-3098 52,-3089 3048,-3089 1184,-3087 759,-3075 831,-3071 2376,-3060 2476,-3060 2555,-3060 2299,-3059 2246,-3055 151,-3054 2761,-3052 3126,-3052 1193,-3051 3048,-3044 1250,-3040 1745,-3019 816,-3011 1769,-2997 729,-2995 1301,-2984 1743,-2976 60,-2971 792,-2958 131,-2957 1287,-2953 2492,-2952 2766,-2952 2329,-2942 2227,-2940 2132,-2932 863,-2924 2589,-2920 727,-2916 1972,-2914 2022,-2907 678,-2902 3040,-2887 1390,-2862 309,-2861 58,-2854 1273,-2854 2751,-2852 1181,-2839 1993,-2830 2369,-2813 1151,-2810 1274,-2809 677,-2802 1557,-2800 3008,-2799 2490,-2798 2773,-2790 1836,-2788 3334,-2785 92,-2777 60,-2709 1455,-2702 679,-2700 2486,-2699 1111,-2695 1162,-2688 1284,-2688 1941,-2670 1990,-2670 2203,-2667 1745,-2657 3013,-2651 1666,-2646 1284,-2643 2133,-2634 1991,-2626 1937,-2625 1720,-2622 1397,-2617 641,-2602 1694,-2590 2390,-2589 1304,-2584 1185,-2576 2161,-2550 3015,-2550 1979,-2528 1246,-2526 1007,-2509 2202,-2501 2378,-2497 1085,-2479 3320,-2479 52,-2477 2282,-2476 3011,-2451 1006,-2447 2220,-2424 1107,-2386 1039,-2379 1180,-2377 2131,-2365 2378,-2352 2130,-2335 2319,-2317 53,-2305 1155,-2301 1207,-2301 1236,-2301 2130,-2300 1085,-2276 3326,-2262 2384,-2260 2117,-2249 1053,-2231 2321,-2227 1174,-2223 1111,-2213 2150,-2192 1147,-2155 3014,-2152 926,-2150 1087,-2150 1948,-2139 2474,-2135 2150,-2125 2348,-2125 1923,-2116 50,-2098 323,-2050 1002,-2049 3233,-2040 2053,-2009 2143,-2007 3325,-2006 1650,-1981 2739,-1957 2480,-1954 647,-1952 320,-1950 55,-1946 2148,-1931 2082,-1926 1062,-1888 2129,-1877 1207,-1874 2279,-1874 320,-1859 2737,-1854 3230,-1853 2130,-1843 1064,-1841 215,-1834 1207,-1814 1235,-1814 2129,-1812 2212,-1809 3104,-1793 58,-1771 2141,-1766 336,-1758 1013,-1747 609,-1734 663,-1734 2272,-1724 1077,-1711 3340,-1702 3248,-1696 386,-1694 1007,-1670 670,-1668 607,-1664 299,-1654 3102,-1654 2402,-1651 1179,-1624 2143,-1611 68,-1610 1934,-1597 1595,-1591 1938,-1565 1390,-1556 345,-1555 1330,-1555 1256,-1552 1556,-1542 1770,-1515 1365,-1509 2393,-1500 1202,-1499 2209,-1493 1303,-1492 1746,-1491 1122,-1488 349,-1454 1715,-1432 2485,-1432 2381,-1427 50,-1424 3335,-1419 1652,-1418 3245,-1416 151,-1404 1390,-1394 1882,-1380 617,-1354 1955,-1353 350,-1351 2345,-1335 2476,-1314 1883,-1312 2236,-1308 1982,-1306 2127,-1300 1261,-1266 1956,-1252 368,-1250 2477,-1241 141,-1238 2336,-1218 1527.5,-1216.5 2248,-1216 49,-1201 2176,-1200 1526.5,-1184.5 314,-1162 3313,-1162 2997,-1151 645,-1148 917,-1137 2387,-1119 128,-1105 361,-1102 962,-1102 647,-1084 234,-1064 2997,-1052 921,-1049 2403,-1024 3244,-979 1075,-970 1537,-927 103,-923 1426.72,-902.34 1874.1,-902.03 2215,-898 389,-895 234,-879 2108,-851 3014,-843 1827,-835 1686,-824 2178,-822 1909,-821 2025,-816 1080,-813 2433,-811 3246,-806 1396,-791 1434,-791 2724,-786 1256,-774 379,-771 1716,-761 1844,-756 288,-748 1103,-748 3028,-747 626,-745 935,-744 1352,-744 3095,-736 2433,-735 2740,-723 2335,-715 1394,-699 2246,-694 2467,-691 3003,-690 3317,-677 621,-651 361,-649 105,-646 2168,-631 1246,-614 2349,-604 965,-600 2742,-581 2245,-578 2451,-578 1425,-562 1484,-555 1096,-537 1554,-523 1495,-513 2461,-503 2321,-498 3257,-494 644,-483 902,-461 1246,-450 347,-443 1496,-434 2176,-433 3033,-428 2733,-426 2305,-393 1413,-387 1487,-382 1560,-353 83,-343 2473,-342 1037,-331 3179,-331 3316,-322 2379,-315 753,-306 306,-278 1664,-276 1536,-274 2739,-269 1257,-266 1364,-225 2051,-221 1017,-184 712,-159 1838,-134 333,-95 1227,-87 3056,-87 1722,-84 2376,-82 886,-79 2686,-75 2057,-71
  other v2: 1359,-564 1361,-524 1360,-488 1359,-456 1359,-424 1359,-387 1404,-356 1436,-356 1359,-355 1756,-260 1755,-235
  other v3: 1139,-2931 2144.53,-340
IOREF: CN8.3 IOREF.1 | length 535.3
  Top Layer w5: IOREF.1@225,-601 691,-601 CN8.3@740,-650
MRAM_CEB: IC4.8 MRAM_CEb.1 R130.2 R131.2 R135.1 | length 4334.8
  Top Layer w5: MRAM_CEb.1@225,-1500 229,-1504 R135.1@608,-1504
  Top Layer w18: IC4.8@1492.02,-2335 v1(1492.02,-2262.46)
  INT1 w5: MRAM_CEb.1@225,-1500 172,-1553 172,-1866 205,-1899 874,-1899 959,-1814 959,-1520 1017,-1462 1371,-1462 1531,-1622 1531,-1682 1483,-1730 1211,-1730 1178,-1763 1178,-1826 1197,-1845 1258,-1845 1296,-1883 1296,-2099 1324,-2127 1706,-2127 1727,-2148 1727,-2207 1708,-2226 1528.48,-2226 v1(1492.02,-2262.46)
  Bottom Layer w15: R131.2@1465.94,-2262.46 v1(1492.02,-2262.46) R130.2@1492.02,-2226.46
MRAM_CEb_1: CN9.2 R135.2 | length 194.4
  Top Layer w5: R135.2@668,-1504 786,-1504 CN9.2@840,-1450
MRAM_LBB: IC4.47 MRAM_LBb.1 R126.1 R133.2 R134.2 | length 4349.9
  Top Layer w5: IC4.47@1492.02,-1845 1492.02,-2037.02 1522,-2067 2393,-2067 2440,-2114 2440,-3388 2252,-3576 2252,-3762 2291,-3801 2531,-3801 2574,-3758 2574,-3491 2614,-3451 R126.1@2709,-3451 2709,-3413 2720,-3402 3070,-3402 MRAM_LBb.1@3170,-3302
  Top Layer w18: IC4.47@1492.02,-1845 v1(1491.98,-1774.46)
  Bottom Layer w15: R134.2@1465.9,-1774.46 v1(1491.98,-1774.46) R133.2@1491.98,-1738.46
MRAM_LBb_1: CN12.67 R126.2 | length 54
  Top Layer w30: R126.2@2769,-3451 CN12.67@2823,-3451
MRAM_OE: JP6.1 U6.6 | length 131.9
  Top Layer w20: JP6.1@2131,-936 2188.82,-993.82 U6.6@2239,-993.82
MRAM_OE_2: JP6.2 R143.2 U1.11 U2.11 | length 4138.5
  Top Layer w5: v1(1752.37,-902.03) 1825.97,-902.03 1859,-869 2023,-869 2063,-909 2063,-968 JP6.2@2131,-1036
  Top Layer w11.8: v1@1505.33,-3294.82 U2.11@1554.55,-3294.82 ; U1.11@1702.55,-902.18 v1@1751.92,-902.18
  INT2 w5: v1(1505.63,-3294.97) 1454.97,-3294.97 1443,-3283 1443,-3006 1355,-2918 1180,-2918 931,-2669 931,-2214 889,-2172 889,-1408 990,-1307 1274,-1307 1324,-1257 1324,-1060 1423,-961 1571,-961 1627.47,-904.53 v1@1754.87,-904.53
  Bottom Layer w25: JP6.2@2131,-1036 R143.2@2208.5,-1053.5
MRAM_OEB: IC4.49 JP5.2 MRAM_OEb.1 R120.1 R121.2 R122.2 | length 4380.1
  Top Layer w5: MRAM_OEb.1@225,-1700 313,-1788 392,-1788 404,-1800 R120.1@613,-1800 613,-1883 631,-1901 892,-1901 913,-1880 913,-1487 951,-1449 1212,-1449 1293,-1530 1293,-1709 1266,-1736 1146,-1736 1106,-1776 1106,-2078 1144,-2116 1393,-2116 1429.03,-2079.97 IC4.49@1429.03,-1845
  Top Layer w18: IC4.49@1429.03,-1845 v1(1428.98,-1774.46)
  INT1 w5: MRAM_OEb.1@225,-1700 225,-1755 273,-1803 882,-1803 933,-1752 933,-1501 1005,-1429 1060,-1429 JP5.2@1131,-1358
  Bottom Layer w15: R122.2@1402.91,-1774.46 v1(1428.98,-1774.46) R121.2@1428.98,-1738.46
MRAM_OEb_1: CN9.8 JP5.1 JP6.3 R120.2 R143.1 U6.1 | length 2135.6
  Top Layer w5: R120.2@663,-1815 673,-1805 R120.2@673,-1800 790,-1800 CN9.8@840,-1750 ; JP5.1@1031,-1358 1082,-1307 1346,-1307 1419,-1380 1764,-1380 1959.5,-1184.5 2082.5,-1184.5 JP6.3@2131,-1136
  Top Layer w20: JP6.3@2131,-1136 2170.82,-1096.18 U6.1@2239,-1096.18
  INT1 w5: CN9.8@840,-1750 906,-1684 906,-1483 JP5.1@1031,-1358
  Bottom Layer w25: JP6.3@2131,-1136 R143.1@2208.5,-1113.5
MRAM_OEb_ALT: CN12.30 JP5.3 MRAM_OEb_ALT.1 | length 2039.2
  Top Layer w5: CN12.30@2940,-1551 3121,-1551 MRAM_OEb_ALT.1@3170,-1502
  Bottom Layer w5: JP5.3@1231,-1358 1331,-1458 2455,-1458 2496,-1499 2888,-1499 CN12.30@2940,-1551
MRAM_SEB: IC4.36 JP4.2 MRAM_SEb.1 R10.2 R11.2 R129.1 R142.2 | length 4395.3
  Top Layer w5: JP4.2@1002,-2937 915,-2850 915,-2656 856,-2597 675,-2597 608,-2530 R129.1@608,-2401 607,-2400 MRAM_SEb.1@225,-2400 126,-2301 126,-1509 186,-1449 250,-1449 302,-1397 874,-1397 908,-1431 1609,-1431 1838.48,-1660.48 IC4.36@1838.48,-1845
  Top Layer w18: v1(1838.48,-1915.54) IC4.36@1838.48,-1845
  Bottom Layer w15: R10.2@1838.48,-1951.54 v1(1838.48,-1915.54) R11.2@1864.56,-1915.54
  Bottom Layer w25: JP4.2@1002,-2937 R142.2@1089,-2916
MRAM_SEb_1: CN9.24 JP4.3 R129.2 R142.1 | length 721.4
  Top Layer w5: R129.2@668,-2401 668,-2477 693,-2502 792,-2502 CN9.24@840,-2550 934,-2644 934,-2769 JP4.3@1002,-2837
  Bottom Layer w25: JP4.3@1002,-2837 R142.1@1089,-2856
MRAM_UBB: IC4.48 MRAM_UBb.1 R123.1 R127.2 R128.2 | length 4325.4
  Top Layer w5: v1(1460.53,-1915.54) 1460.53,-2072.53 1476,-2088 2378,-2088 2419,-2129 2419,-3377 2232,-3564 2232,-3798 2263,-3829 2549,-3829 2592,-3786 2592,-3518 2611,-3499 3060,-3499 3076,-3515 R123.1@3076,-3551
  Top Layer w18: v1(1460.53,-1915.54) IC4.48@1460.53,-1845
  Top Layer w20: R123.1@3076,-3551 3121,-3551 MRAM_UBb.1@3170,-3502
  Bottom Layer w15: R128.2@1434.45,-1915.54 v1(1460.53,-1915.54) R127.2@1460.53,-1951.54
MRAM_UBb_1: CN12.70 R123.2 | length 76
  Top Layer w30: CN12.70@2940,-3551 R123.2@3016,-3551
MRAM_WEB: IC4.19 MRAM_WEb.1 R124.2 R125.2 R132.1 | length 4328.7
  Top Layer w5: R132.1@610,-1601 225,-1601 MRAM_WEb.1@225,-1600 176,-1600 151,-1625 151,-2021 178,-2048 246,-2048 275,-2019 275,-1836 288,-1823 354,-1823 371,-1840 371,-1969 400,-1998 1015,-1998 1041,-2024 1041,-2177 1022,-2196 930,-2196 912,-2214 912,-2582 953,-2623 953,-2733 984,-2764 1803,-2764 1838.48,-2728.52 v1@1838.48,-2404.54
  Top Layer w18: v1@1838.48,-2404.54 IC4.19@1838.48,-2335
  Bottom Layer w15: R124.2@1838.93,-2440.54 v1(1838.93,-2404.54) R125.2@1865.01,-2404.54
MRAM_WEb_1: CN9.6 R132.2 | length 190.3
  Top Layer w5: R132.2@670,-1601 791,-1601 CN9.6@840,-1650
NC1: IC4.25 TP1.1 | length 479.8
  Top Layer w5: IC4.25@2027.46,-2335 2027.46,-2774.46 TP1.1@2056,-2803
NC2: IC4.30 TP6.1 | length 470.6
  Top Layer w5: TP6.1@2009,-1382 2009,-1723.05 2027.41,-1741.46 IC4.30@2027.41,-1845
NetJP12_2: JP12.2 R16.2 R140.1 | length 214.7
  Top Layer w25: JP12.2@1464.35,-204 R16.2@1641,-204
  Bottom Layer w15: JP12.2@1464.35,-202.65 1464.35,-164.65
NetLED2_A: LED2.A R12.1 | length 97.5
  Top Layer w30: R12.1@2232,-303.78 LED2.A@2232,-206.24
NetR13_1: R13.1 R15.1 | length 60
  Top Layer w20: R15.1@1941.15,-265 R13.1@1941.15,-205
NetR14_1: R14.1 R15.2 R17.2 U3.5 | length 145.1
  Top Layer w25: R14.1@1819,-367 R17.2@1819,-283 ; R17.2@1819,-264 R15.2@1880.15,-264
NetR16_1: R16.1 R17.1 | length 118
  Top Layer w25: R16.1@1701,-204 R17.1@1819,-204
OE_BUFb: CN12.62 OE_BUFb.1 U4.1 U4.19 U5.1 U5.19 | length 4499.6
  Top Layer w15: U4.19@1200.5,-1106.91 v1@1249.72,-1106.91 ; v1@1426.87,-1132.5 U4.1@1476.09,-1132.5 ; U5.1@1784.41,-3067 v1@1833.63,-3067 ; v1@2010.78,-3092.59 U5.19@2060,-3092.59
  INT2 w5: v1(1426.72,-1132.65) 1557.65,-1132.65 1601,-1176 1601,-1317 1495,-1423 1495,-1611 1463,-1643 1279,-1643 1153,-1769 1153,-1912 1188,-1947 1188,-2193 1368,-2373 1368,-2432 1407,-2471 1407,-2580 1801,-2974 1801,-3034.06 v1(1833.78,-3066.85) 1859.38,-3092.44 v1(2010.63,-3092.44)
  Bottom Layer w5: v1(1249.87,-1107.06) 1275.46,-1132.65 v1(1426.72,-1132.65) ; v1(2010.63,-3092.44) 2116.19,-3198 2648,-3198 2680,-3230 2768,-3230 2803,-3195 2896,-3195 CN12.62@2940,-3151 3046,-3151 3095,-3102 OE_BUFb.1@3170,-3102
OE_DFFb: CN9.11 JP5.4 OE_DFFb.1 U1.1 U2.1 | length 4725.5
  Top Layer w11.8: v1@1284.86,-3064.5 U2.1@1334.08,-3064.5 ; U1.1@1923.02,-1132.5 U1.1@1923.47,-1132.5 v1@1972.24,-1132.5
  INT2 w5: OE_DFFb.1@225,-2000 690,-2000 CN9.11@740,-1950 ; v1(1285.15,-3064.65) 1285.15,-3017.15 1247,-2979 872,-2979 797,-2904 797,-2007 CN9.11@740,-1950 ; v1(1972.85,-1132.35) 1991.5,-1151 2032,-1151 2062,-1121 2062,-919 2014,-871 1408,-871 1277,-1002 1277,-1187 1206,-1258 JP5.4@1131,-1258 997,-1258 949,-1306 833,-1306 791,-1348 791,-1899 CN9.11@740,-1950
R\S\T\: CN8.5 RSTB.1 | length 535.7
  Top Layer w5: RSTB.1@225,-700 690,-700 CN8.5@740,-750
SHDN: CN9.28 JP2.1 R144.2 | length 2593
  Bottom Layer w5: CN9.28@840,-2750 896,-2694 896,-1262 961,-1197 1425,-1197 1488,-1134 R144.2@1488,-788
  Bottom Layer w25: JP2.1@1462,-701 R144.2@1488,-788
SHDN_1: JP2.2 R144.1 SHDN1.1 U3.1 | length 449.2
  Top Layer w25: SHDN1.1@1623.5,-821.5 1562,-760 JP2.2@1562,-701 1562,-608.42 1594.29,-576.13 U3.1@1671.11,-576.13
  Bottom Layer w25: R144.1@1548,-788 JP2.2@1562,-701
V18: IC4.27 R141.2 TP3.1 | length 580.8
  Top Layer w15: 2090.45,-2389 2090.45,-2680.45 TP3.1@2212,-2802
  Top Layer w18: v1(2090.45,-2415) IC4.27@2090.45,-2335
  Bottom Layer w18: R141.2@2090.9,-2452.45 v1@2090.9,-2415
VCC: C7.1 C8.1 C9.1 C10.1 C15.1 C16.1 C21.1 C22.1 C23.1 C24.1 C25.1 C26.1 C27.1 C28.1 C29.1 C30.1 IC4.13 IC4.41 L2.2 pad.1@3168,-605 R2.1 R5.1 R8.1 R10.1 R19.1 R22.1 R25.1 R28.1 R31.1 R34.1 R37.1 R40.1 R43.1 R46.1 R49.1 R52.1 R55.1 R58.1 R61.1 R64.1 R67.1 R70.1 R73.1 R76.1 R79.1 R82.1 R85.1 R88.1 R91.1 R94.1 R97.1 R100.1 R103.1 R106.1 R109.1 R112.1 R115.1 R118.1 R121.1 R124.1 R127.1 R130.1 R133.1 R137.1 U1.20 U2.20 U4.20 U5.20 U6.5 VCC.1 | length 806.4
  Top Layer w15: C30.1@1120.5,-1132.5 U4.20@1200.5,-1132.5 ; U2.20@1555,-3064.5 1630.81,-3064.5 C8.1@1630.81,-3051.5 C7.1@1630.81,-3004.5 ; C10.1@1629.69,-1195 1629.69,-1135 U1.20@1705.5,-1135 ; U5.20@2060,-3067 C28.1@2140,-3067
  Top Layer w18: v1(1649.5,-2431) IC4.13@1649.5,-2335 ; IC4.41@1680.95,-1828 v1(1680.95,-1748)
  Top Layer w20: U6.5@2289,-993.82 C15.1@2289,-908 C16.1@2289,-843 C16.1@2289,-841
  Top Layer w25: C16.1@2289,-841 v3(2289,-795)
  other v1: 2101.19,-3043.5 2053.19,-3036.5 1544,-3034 1580,-3032 2083.19,-3007.5 1574,-3005 2068,-2924 1261,-2479 1555.45,-2479 1745.45,-2479 2003.45,-2479 1366.45,-2478 1934.45,-2478 1398,-2189 1966,-2189 1587,-2188 1777,-2188 1264,-2187 2100,-2187 1233,-1994 1556,-1993 1742,-1993 1871,-1993 1367,-1992 2005,-1992 1397.95,-1701 1586.95,-1700 1263.95,-1699 1774.95,-1699 1963.95,-1698 2031.95,-1698 1686.5,-1194.5 1155,-1170 1190,-1170 1220,-1170 1716.5,-1165.5 1668.5,-1158.5
  other v2: 1941,-362 2062,-359.69 2088,-346 1941,-335 2062,-332 1909,-331 1929,-313 1959,-313 2048,-310 2087,-310
VDD: IC4.29 TP5.1 | length 554
  Top Layer w15: IC4.29@2058.95,-1845 TP5.1@2058.95,-1291
VIN: C11.1 C12.1 JP2.3 L1.2 R12.2 U3.2 VIN.1 | length 590.6
  Top Layer w30: JP2.3@1662,-701 1663,-701 1707,-657 C11.1@1772,-657 ; 1939,-573 VIN.1@2012,-573 2164,-573 2232,-505 R12.2@2232,-363.78
  other v2: 1894,-555 1926,-555 1751,-552 1783,-552 1820,-552 1852,-552 1905,-527 1937,-527 1837,-526.13 1869,-526.13 1768,-525 1800,-525
VINTH: IC4.26 TP2.1 | length 547.1
  Top Layer w15: IC4.26@2058.95,-2335 2058.95,-2708.95 2133.95,-2783.95 TP2.1@2133.95,-2851
VOUT: C13.1 C14.1 L2.1 R14.2 U3.4 VOUT.1 | length 333.1
  Top Layer w25: U3.4@1671.11,-426.13 v2(1748,-426.13) ; v2(1774.13,-426.13) 1966.13,-426.13 VOUT.1@2007,-467 VOUT.1@2013.37,-467
  other v2: 2058,-499 2099,-494 1883,-468 2063,-468 2118,-465.38 1861,-451.01 1944,-449 2114,-429 1858.99,-424 1954,-420 2083,-420 2047,-419 1995,-414
VPP: IC4.28 TP4.1 | length 489.9
  Top Layer w5: TP4.1@2134.5,-1391.5 TP4.1@2143,-1383
  Top Layer w15: IC4.28@2090.45,-1845 2090.45,-1414.55 TP4.1@2124,-1381
pads on no net: CN7.1 CN7.2 CN7.3 CN7.4 CN7.5 CN7.6 CN7.7 CN7.9 CN7.10 CN7.11 CN7.12 CN7.13 CN7.14 CN7.15 CN7.17 CN7.19 CN8.1 CN8.2 CN8.4 CN8.6 CN8.7 CN8.8 CN8.10 CN8.12 CN8.15 CN9.1 CN9.3 CN9.4 CN9.5 CN9.7 CN9.9 CN9.10 CN9.13 CN9.14 CN9.15 CN9.17 CN9.19 CN9.20 CN9.21 CN9.23 CN9.26 CN10.1 CN10.3 CN10.7 CN10.9 CN10.11 CN10.13 CN10.14 CN10.15 CN10.16 CN10.20 CN10.25 CN10.29 CN10.31 CN10.32 CN10.33 CN10.34 CN11.1 CN11.2 CN11.3 CN11.4 CN11.5 CN11.6 CN11.7 CN11.9 CN11.10 CN11.11 CN11.12 CN11.13 CN11.14 CN11.15 CN11.16 CN11.17 CN11.18 CN11.21 CN11.23 CN11.24 CN11.25 CN11.26 CN11.27 CN11.28 CN11.29 CN11.30 CN11.31 CN11.32 CN11.33 CN11.34 CN11.35 CN11.36 CN11.37 CN11.38 CN11.39 CN11.40 CN11.41 CN11.42 CN11.43 CN11.44 CN11.45 CN11.46 CN11.47 CN11.48 CN11.49 CN11.50 CN11.54 CN11.55 CN11.56 CN11.57 CN11.58 CN11.59 CN11.61 CN11.62 CN11.63 CN11.64 CN11.65 CN11.66 CN11.67 CN11.68 CN11.70 CN12.1 CN12.2 CN12.3 CN12.4 CN12.5 CN12.6 CN12.7 CN12.8 CN12.11 CN12.12 CN12.13 CN12.14 CN12.15 CN12.16 CN12.17 CN12.18 CN12.19 CN12.21 CN12.22 CN12.23 CN12.24 CN12.25 CN12.26 CN12.27 CN12.28 CN12.29 CN12.31 CN12.32 CN12.33 CN12.34 CN12.35 CN12.37 CN12.40 CN12.41 CN12.42 CN12.43 CN12.45 CN12.46 CN12.47 CN12.48 CN12.49 CN12.50 CN12.51 CN12.52 CN12.53 CN12.55 CN12.56 CN12.57 CN12.59 CN12.60 CN12.61 CN12.64 CN12.66 IC4. IC4.GUIDEPIN_1.6NP IC4.ORIGIN JP4.1 R2. R3. R5. R6. R8. R9. R10. R11. R19. R20. R22. R23. R25. R26. R28. R29. R31. R32. R34. R35. R37. R38. R40. R41. R43. R44. R46. R47. R49. R50. R52. R53. R55. R56. R58. R59. R61. R62. R64. R65. R67. R68. R70. R71. R73. R74. R76. R77. R79. R80. R82. R83. R85. R86. R88. R89. R91. R92. R94. R95. R97. R98. R100. R101. R103. R104. R106. R107. R109. R110. R112. R113. R115. R116. R118. R119. R121. R122. R124. R125. R127. R128. R130. R131. R133. R134. R137. R138. U6.4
